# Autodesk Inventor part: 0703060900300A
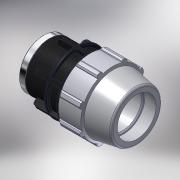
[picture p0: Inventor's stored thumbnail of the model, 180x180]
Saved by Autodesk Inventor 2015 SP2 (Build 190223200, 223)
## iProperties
Created: 2017-02
Part Number: 0703060900300A
Material: PVC-Piping
Description: PLASSON FEMALE ADAPTOR 90-3"
Document SubType Name: Modeling
Designer: KIM
Mass: 92.6774 g
Surface Area: 199.44 cm^2
Volume: 66.1981 cm^3
Density: 1.4 g/cm^3
Appearance: PTFE
Author: KIM
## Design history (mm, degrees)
derived "87030.ipt"
feature "Solid1::87030.ipt"
tag "TaggingFeature1"
body "Solid1"
other parameters: "d4" = 31.85714, "d5" = 55.75, "d7" = 154, "d9" = 31.85714, "d11" = 6.37143, "d12" = 123.2, "d13" = 120 deg, "d14" = 117, "d15" = 10 deg, "d16" = 138.6, "d18" = 4.5, "d19" = 35 deg, "d20" = 17.5 deg, "d21" = 143.22, "d23" = 0, "d25" = 360 deg, "d27" = 3.08, "d34" = 7.7, "d35" = 66.9, "d36" = 0, "d42" = 55.75, "d43" = 4.62, "d46" = 2.7, "d49" = 183, "d51" = 223, "d53" = 1.8, "d55" = 360 deg, "d62" = 84.926, "d63" = 84.926, "d64" = 74.33333, "d65" = 7.7, "d69" = 110.88, "d70" = 3.85, "d71" = 12.6, "d72" = 0.5, "d73" = 1, "E_" = 154, "H_" = 223, "l_" = 183, "Rp_Rc_" = 84.926
